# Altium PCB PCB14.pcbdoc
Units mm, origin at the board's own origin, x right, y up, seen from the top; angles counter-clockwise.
Board outline 66.94 x 54.68 mm, 2 copper layers (Top Layer, Bottom Layer); 73 components, 75 nets, 272 pads, 107 vias.
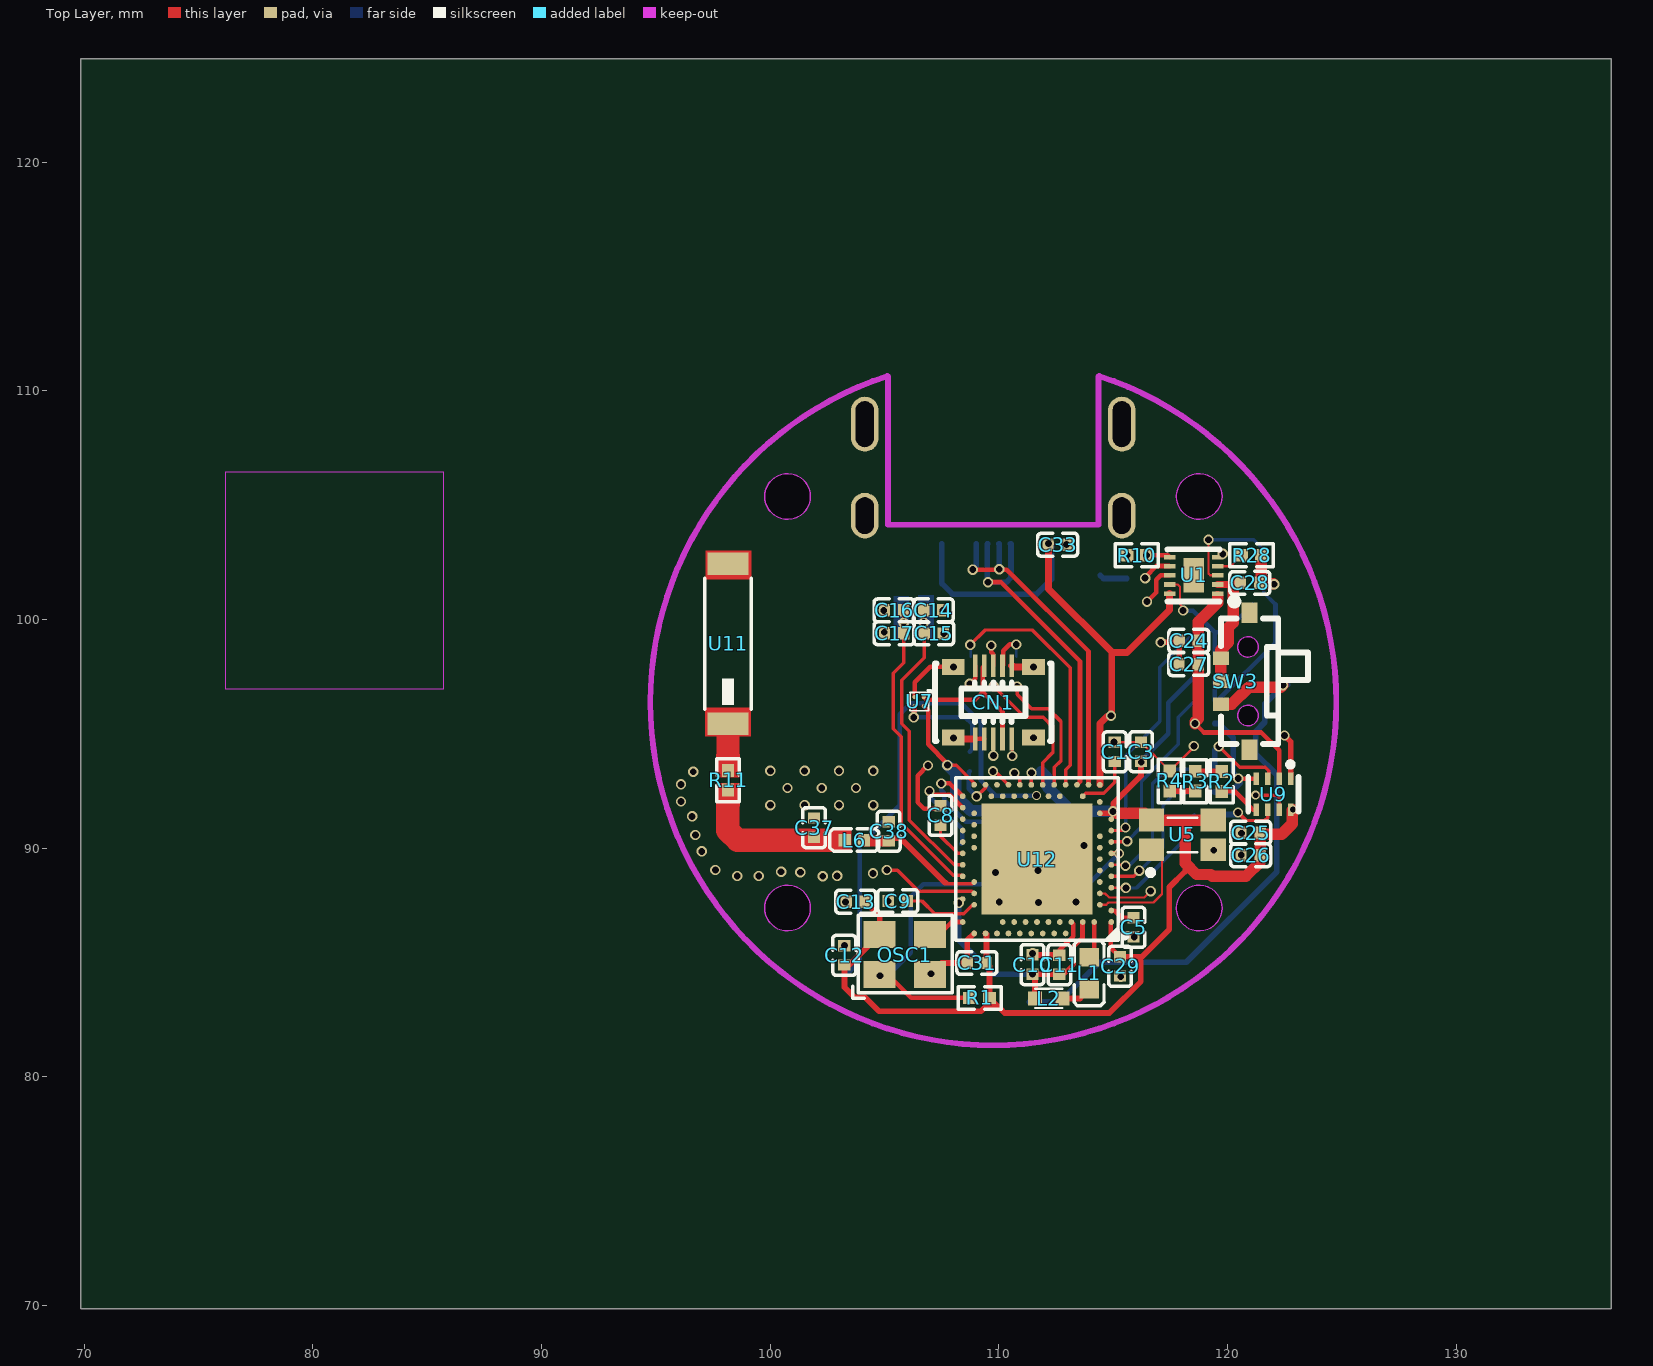
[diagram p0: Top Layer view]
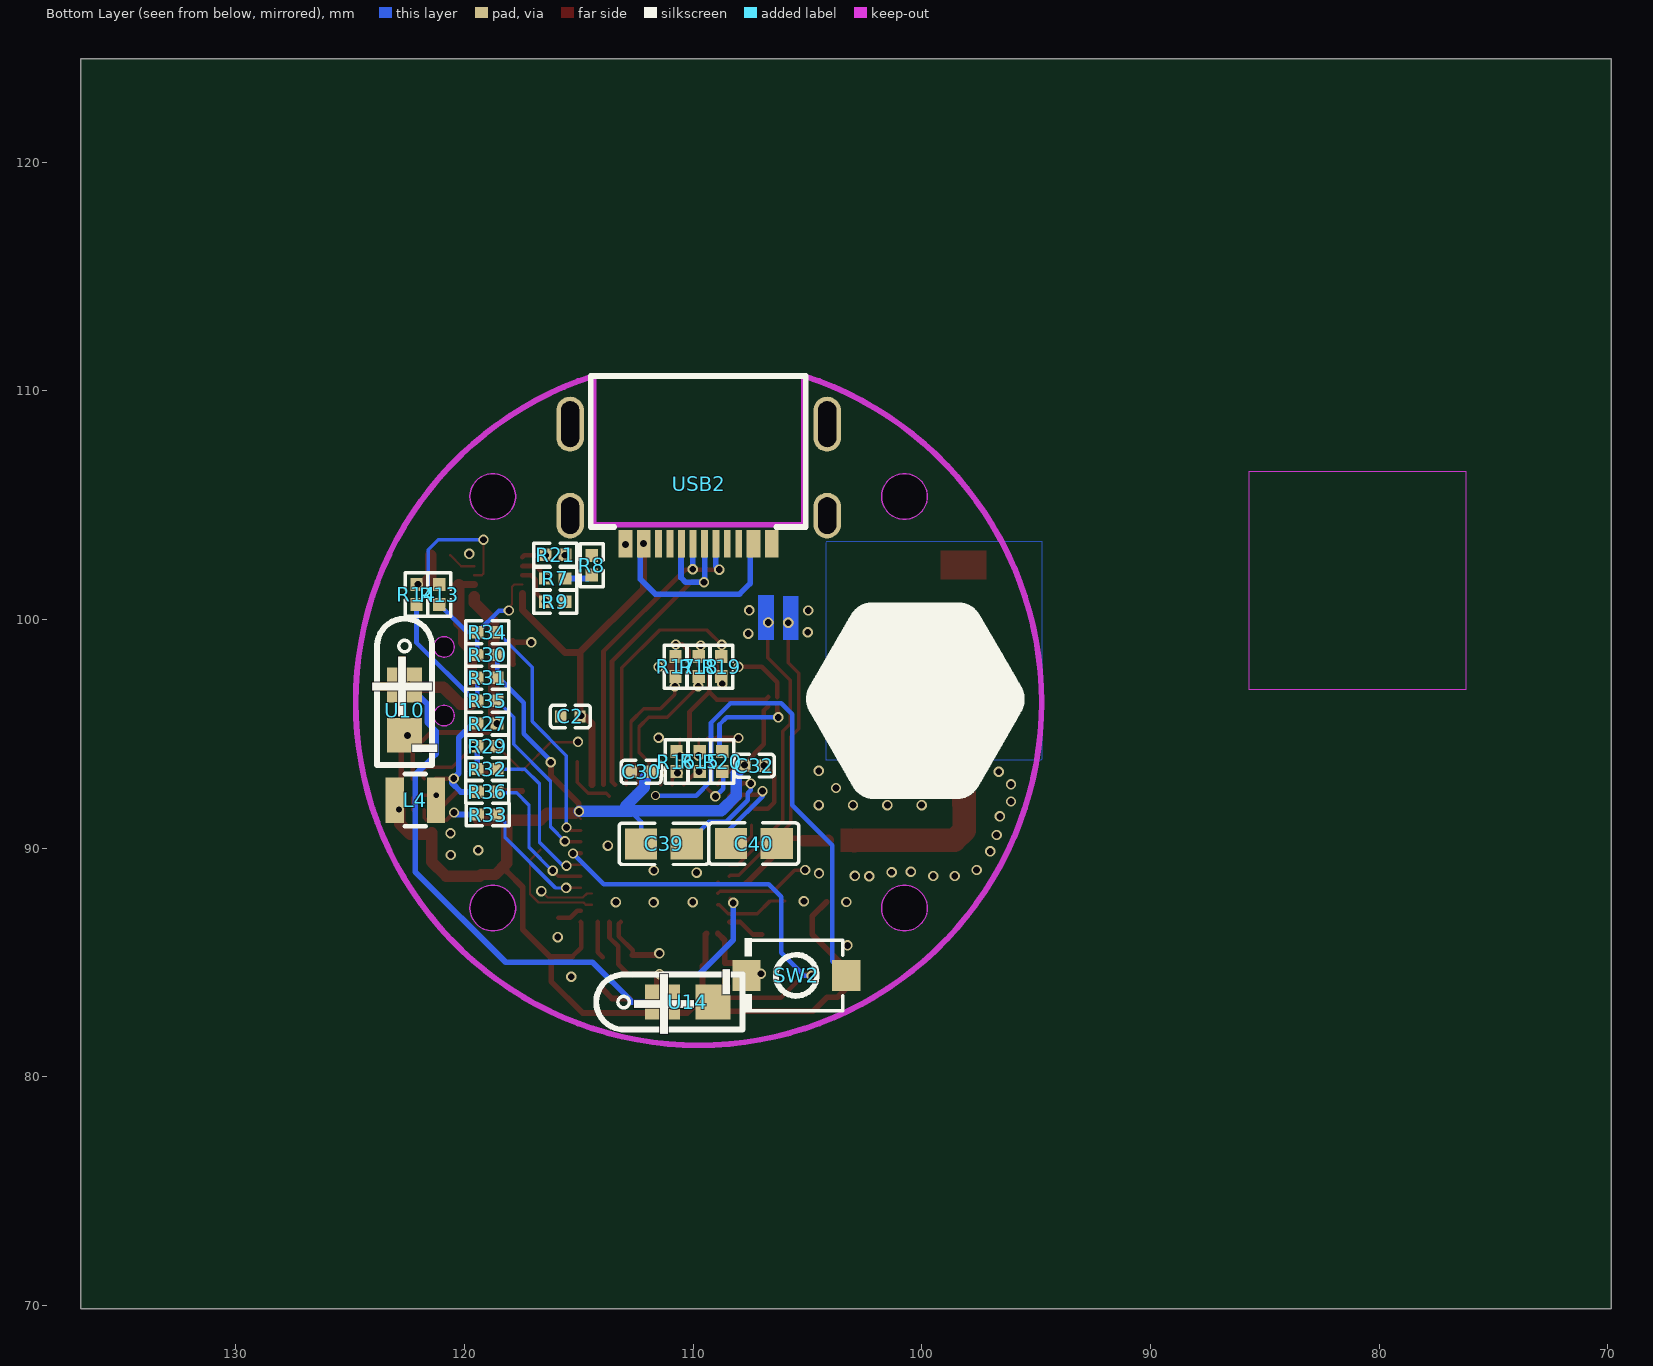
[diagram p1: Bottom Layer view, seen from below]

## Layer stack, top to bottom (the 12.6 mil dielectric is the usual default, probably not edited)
Top Layer: signal copper (thickness not stored)
Dielectric: dielectric 0.32, FR-4, Dk 4.8
Bottom Layer: signal copper (thickness not stored)

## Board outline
136.794,69.85 69.85,69.85 69.85,124.528 136.794,124.528
cut-out: 119.765,105.379 cw(c118.765,105.379) 117.765,105.379 cw(c118.765,105.379)
cut-out: 119.765,87.379 cw(c118.765,87.379) 117.765,87.379 cw(c118.765,87.379)
cut-out: 101.765,87.379 cw(c100.765,87.379) 99.765,87.379 cw(c100.765,87.379)
cut-out: 101.765,105.379 cw(c100.765,105.379) 99.765,105.379 cw(c100.765,105.379)

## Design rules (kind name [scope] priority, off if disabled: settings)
BoardOutlineClearance copperThickness1oz [All] p0: genericclearance=0.254 ignorepadtopadclearanceinfootprint=FALSE except(0: Arc-SplitContinuation Track-SplitContinuation SMDPad-SplitContinuation THPad-SplitContinuation Via-SplitContinuation Fill-SplitContinuation Poly-SplitContinuation Region-SplitContinuation Text-SplitContinuation; 0.152: Track-CutoutEdge SMDPad-CutoutEdge THPad-CutoutEdge Via-CutoutEdge Region-CutoutEdge; 0.3: Track-OutlineEdge SMDPad-OutlineEdge THPad-OutlineEdge Via-OutlineEdge Fill-OutlineEdge Region-OutlineEdge Poly-OutlineEdge Text-OutlineEdge Fill-CutoutEdge)
BoardOutlineClearance copperThickness2oz [All] p0: genericclearance=0.254 ignorepadtopadclearanceinfootprint=FALSE except(0: Arc-SplitContinuation Track-SplitContinuation SMDPad-SplitContinuation THPad-SplitContinuation Via-SplitContinuation Fill-SplitContinuation Poly-SplitContinuation Region-SplitContinuation Text-SplitContinuation; 0.152: Track-CutoutEdge SMDPad-CutoutEdge THPad-CutoutEdge Via-CutoutEdge Region-CutoutEdge; 0.3: Track-OutlineEdge SMDPad-OutlineEdge THPad-OutlineEdge Via-OutlineEdge Fill-OutlineEdge Region-OutlineEdge Poly-OutlineEdge Text-OutlineEdge Fill-CutoutEdge)
Clearance copperThickness1oz [(InNet('GND') OR InNet('DECUSB') OR InNet('VBUS') OR InNet('VDD') OR InNet('DEC1') OR InNet('DEC5') OR InNet('DEC3') OR InNet('DEC4') OR InNet('NFC1') OR InNet('NFC2') OR InNet('ANT') OR InNet('VIN') OR InNet('VBAT') OR InNet('VOUT1') OR InNet('MOSI') OR InNet('CS') OR InNet('MISO') OR InNet('AD_RESET') OR InNet('$1N3350') OR InNet('DCC') OR InNet('$1N6296') OR InNet('CRYST_OE') OR InNet('XC1') OR InNet('$1N6166') OR InNet('$1N6090') OR InNet('$1N6242') OR InNet('$1N7034') OR InNet('$1N6953') OR InNet('$1N7110') OR InNet('$1N7200') OR InNet('STAT2') OR InNet('CE') OR InNet('STAT1') OR InNet('XL1') OR InNet('P0.04') OR InNet('P0.05') OR InNet('SWDCLK') OR InNet('SWDIO') OR InNet('NRESET') OR InNet('D+') OR InNet('D-') OR InNet('OUT_EN') OR InNet('MODE_PWR') OR InNet('EN_PWR') OR InNet('STOP_PWR') OR InNet('$1N13722') OR InNet('DEC2') OR InNet('DCCH') OR InNet('FEED') OR InNet('P0.26') OR InNet('P0.27') OR InNet('P0.06') OR InNet('P0.07') OR InNet('P1.08') OR InNet('P1.09') OR InNet('P1.11') OR InNet('P1.12') OR InNet('P0.14') OR InNet('P0.16') OR InNet('P0.19') OR InNet('P0.21') OR InNet('P0.23') OR InNet('P0.25') OR InNet('P0.13') OR InNet('P0.24') OR InNet('CC1') OR InNet('CC2') OR InNet('SCLK') OR InNet('P0.15') OR InNet('P0.17') OR InNet('P0.20') OR InNet('P0.22') OR InNet('P1.00') OR InNet('VBAT_I') OR InNet('NONE'))] p1: gap=0.178 ignorepadtopadclearanceinfootprint=FALSE except(0.099: Track-Track Track-SMDPad; 0.152: SMDPad-SMDPad Track-THPad SMDPad-THPad THPad-THPad Track-Via SMDPad-Via THPad-Via Via-Via SMDPad-Fill THPad-Fill Via-Fill Fill-Fill Track-Region SMDPad-Region THPad-Region Via-Region Region-Region Track-Poly SMDPad-Poly THPad-Poly Via-Poly Fill-Poly Region-Poly Poly-Poly Track-Text SMDPad-Text THPad-Text Via-Text Fill-Text Region-Text Poly-Text Text-Text; 0.175: SMDPad-Hole THPad-Hole Via-Hole Fill-Hole Region-Hole Poly-Hole Text-Hole Sheet-Hole; 0.201: Track-Hole; 0.3: Track-Fill Fill-Region Track-Sheet SMDPad-Sheet THPad-Sheet Via-Sheet Fill-Sheet Region-Sheet Poly-Sheet Text-Sheet)
Clearance copperThickness2oz [All] p1: gap=0.178 ignorepadtopadclearanceinfootprint=FALSE except(0.152: Track-SMDPad SMDPad-SMDPad Track-THPad SMDPad-THPad THPad-THPad Track-Via SMDPad-Via THPad-Via Via-Via SMDPad-Fill THPad-Fill Via-Fill Fill-Fill Track-Region SMDPad-Region THPad-Region Via-Region Region-Region Track-Poly SMDPad-Poly THPad-Poly Via-Poly Fill-Poly Region-Poly Poly-Poly Track-Text SMDPad-Text THPad-Text Via-Text Fill-Text Region-Text Poly-Text Text-Text; 0.175: Track-Hole SMDPad-Hole THPad-Hole Via-Hole Fill-Hole Region-Hole Poly-Hole Text-Hole Sheet-Hole; 0.203: Track-Track; 0.3: Track-Fill Fill-Region Track-Sheet SMDPad-Sheet THPad-Sheet Via-Sheet Fill-Sheet Region-Sheet Poly-Sheet Text-Sheet)
DiffPairsRouting differentialPair [All] p1: maxuncoupledlength=10 minlimit=6 maxlimit=6 mostfreqgap=6 toplayer_minwidth=5 toplayer_prefwidth=10 toplayer_maxwidth=100 bottomlayer_minwidth=5 bottomlayer_prefwidth=10 bottomlayer_maxwidth=100
PasteMaskExpansion pasteMaskExpansion [All] p1: expansion=0
PlaneConnect innerPlane [All] p1: planeconnectstyle=Relief reliefexpansion=0.508 reliefentries=4 reliefconductorwidth=0.254 reliefairgap=0.254
PolygonConnect copper [All] p1: connectstyle=Direct reliefentries=4 reliefconductorwidth=10 polygonreliefangle="90 Angle" airgapwidth=10
PolygonConnect nocopper [All] p1: connectstyle=No reliefentries=4 reliefconductorwidth=10 polygonreliefangle="90 Angle" airgapwidth=10
PolygonConnect copper_imp [All] p1: connectstyle=Direct reliefentries=4 reliefconductorwidth=10 polygonreliefangle="90 Angle" airgapwidth=10
RoutingVias viaSize [All] p1: viastyle="Through Hole" holewidth=9.8426 minholewidth=3.937 maxholewidth=248.0314 width=15.748 minwidth=7.874 maxwidth=393.7008
SolderMaskExpansion solderMaskExpansion [All] p1: useseparateexpansions=TRUE expansion=2 expansionbottom=2
Width copperThickness1oz [All] p1: maxlimit=100 minlimit=4 preferedwidth=10
Width copperThickness2oz [All] p1: maxlimit=100 minlimit=8 preferedwidth=10

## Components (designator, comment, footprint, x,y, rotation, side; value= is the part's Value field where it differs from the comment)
C1 "CL05A475MP5NRNC" C0402 115.075,94.209 r90 top
C2 "CL05A475MP5NRNC" C0402 115.375,95.759 r0 bottom
C3 "CL05A475MP5NRNC" C0402 116.225,94.219 r90 top
C5 "CL05B104KO5NNNC" C0402 115.895,86.539 r270 top
C8 "0402B102K500NT" C0402 107.455,91.429 r90 top
C9 "0402CG101J500NT" C0402 105.585,87.689 r180 top
C10 "CL05A105KA5NQNC" C0402 111.475,84.909 r270 top
C11 "CL05B104KO5NNNC" C0402 112.655,84.899 r90 top
C12 "CL05B104KO5NNNC" C0402 103.245,85.309 r270 top
C13 "CL05A475MP5NRNC" C0402 103.745,87.659 r0 top
C14 "0402CG101J500NT" C0402 107.134,100.399 r0 top
C15 "0402CG220J500NT" C0402 107.155,99.389 r0 top
C16 "0402CG101J500NT" C0402 105.425,100.399 r180 top
C17 "0402CG220J500NT" C0402 105.425,99.399 r180 top
C24 "CL05A475MP5NRNC" C0402 118.315,99.069 r0 top
C25 "CL05A475MP5NRNC" C0402 121.015,90.679 r0 top
C26 "CL05A475MP5NRNC" C0402 121.015,89.689 r0 top
C27 "CL05A105KA5NQNC" C0402 118.305,98.049 r180 top
C28 "CL05A105KA5NQNC" C0402 120.985,101.599 r0 top
C29 "CL05A105KA5NQNC" C0402 115.305,84.829 r270 top
C30 "CL05B104KO5NNNC" C0402 112.285,93.339 r0 bottom
C31 "CL05B104KO5NNNC" C0402 109.045,84.979 r180 top
C32 "CL05B104KO5NNNC" C0402 107.335,93.609 r180 bottom
C33 "CL05A105KA5NQNC" C0402 112.575,103.269 r0 top
C37 "RF15N0R5A500CT" C0402 101.925,90.899 r90 top
C38 "RF15N0R8B500CT_C396870" C0402 105.185,90.739 r270 top
C39 "CL21A106KAYNNNE_C15850" C0805 111.285,90.189 r180 bottom
C40 "CL21A106KAYNNNE_C15850" C0805 107.355,90.199 r0 bottom
CN1 "513389873" CONN-SMD_513389873 109.765,96.379 r0 top
L1 "LQM18DN100M70L" L0603 113.955,84.529 r90 top
L2 "AISC-0402-15NJ-T" IND-SMD_L1.2-W0.6 112.185,83.429 r0 top
L4 "WIP201610P-2R2ML" IND-SMD_L2.0-W1.6_MHCHL201610A-1R0M-Q8A 122.155,92.099 r0 bottom
L6 "VHF100505HQ4N7ST" L0402 103.685,90.349 r180 top
OSC1 "OT2EL89CJI-111YLC-32M" OSC-SMD_4P-L3.2-W2.5-BL 105.895,85.349 r0 top
R1 "0402WGF2003TCE" R0402 109.165,83.449 r180 top
R2 "0402WGF2003TCE" R0402 119.755,92.919 r90 top
R3 "0402WGF3302TCE" R0402 118.595,92.929 r270 top
R4 "0402WGF3302TCE" R0402 117.482,92.938 r90 top
R7 "0402WGF5102TCE" R0402 116.037,101.791 r180 bottom
R8 "0402WGF5101TCE" R0402 114.435,102.369 r90 bottom
R9 "0402WGF5100TCE" R0402 116.035,100.779 r180 bottom
R10 "0402WGF1002TCE" R0402 116.037,102.807 r180 top
R11 "CRCW04020000Z0EDHP" R0402 98.164,92.97 r90 top
R13 "CRCW04020000Z0EDHP" R0402 121.105,101.089 r270 bottom
R14 "CRCW04020000Z0EDHP" R0402 122.105,101.089 r270 bottom
R15 "CRCW04020000Z0EDHP" R0402 109.725,93.789 r90 bottom
R16 "CRCW04020000Z0EDHP" R0402 110.735,93.789 r90 bottom
R17 "CRCW04020000Z0EDHP" R0402 110.775,97.939 r90 bottom
R18 "CRCW04020000Z0EDHP" R0402 109.765,97.939 r90 bottom
R19 "CRCW04020000Z0EDHP" R0402 108.775,97.939 r270 bottom
R20 "CRCW04020000Z0EDHP" R0402 108.735,93.789 r90 bottom
R21 "0402WGF1002TCE" R0402 116.042,102.829 r180 bottom
R27 "0402WGF2003TCE" R0402 119.015,95.449 r0 bottom
R28 "0402WGF2003TCE" R0402 121.055,102.809 r0 top
R29 "0402WGF2003TCE" R0402 119.015,94.449 r180 bottom
R30 "0402WGF2003TCE" R0402 119.015,98.449 r0 bottom
R31 "0402WGF2003TCE" R0402 119.015,97.449 r0 bottom
R32 "CRCW04020000Z0EDHP" R0402 119.015,93.459 r0 bottom
R33 "CRCW04020000Z0EDHP" R0402 118.995,91.469 r0 bottom
R34 "CRCW04020000Z0EDHP" R0402 119.015,99.439 r0 bottom
R35 "CRCW04020000Z0EDHP" R0402 119.015,96.449 r0 bottom
R36 "CRCW04020000Z0EDHP" R0402 119.005,92.459 r0 bottom
SW2 "TS-1088-AR02016" SW-SMD_L3.9-W3.0-P4.45 105.495,84.439 r0 bottom
SW3 "MK-11C04-G013" SW-SMD_MK-11C04-G013 120.345,97.299 r90 top
U1 "BQ25185DLHR" WSON-10_L2.2-W2.0-P0.40-BL-EP_TI_DLH0010A 118.525,101.929 r90 top
U5 "OV-7604-C7-32.768kHz-20PPM-TA-QC" OSC-SMD_4P-L3.2-W1.5-BL 118.035,90.579 r0 top
U7 "TPS22916BYFPR" DSBGA-4_L0.8-W0.8-R2-C2-P0.40-BL 106.525,96.409 r180 top
U9 "TPS62840DLCR" VSON-8_L2.0-W1.5-P0.50-BL 122.015,92.359 r180 top
U10 "CSSMR950SH_CONN" CSSMR950SH_CONN 122.625,93.839 r180 bottom
U11 "2450AT43A100E" ANT-SMD_L7.0-W2.0-R 98.164,98.939 r270 top
U12 "NRF52840-QIAA-R7" AQFN-73_L7.0-W7.0-P0.50-BL-EP4.8 111.675,89.521 r90 top
U14 "CSSMR950SH_CONN" CSSMR950SH_CONN 108.045,83.269 r90 bottom
USB2 "TYPE-C-31-M-13" USB-C-SMD_TYPE-C-31-M-13 109.765,105.929 r0 bottom

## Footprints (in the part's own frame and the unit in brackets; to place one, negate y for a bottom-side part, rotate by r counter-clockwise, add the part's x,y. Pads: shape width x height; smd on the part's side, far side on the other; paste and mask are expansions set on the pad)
ANT-SMD_L7.0-W2.0-R [mm]
  rect 1x1.8 smd: 1(3.5,0) 2(-3.5,0)
  silkscreen extent -2.86,-1.02 2.86,1.02
AQFN-73_L7.0-W7.0-P0.50-BL-EP4.8 [mm]
  rect 4.85x4.85 smd: 0(0,0)
  round 0.25 smd: A8(-3.25,-1.25) A10(-3.25,-0.75) A12(-3.25,-0.25) A14(-3.25,0.25) A16(-3.25,0.75) A18(-3.25,1.25) A20(-3.25,1.75) A22(-3.25,2.25) A23(-3.25,2.75) AA24(2.25,3.25) AB2(2.5,-2.75) AC5(2.75,-2) AC9(2.75,-1) AC11(2.75,-0.5) AC13(2.75,0) AC15(2.75,0.5) AC17(2.75,1) AC19(2.75,1.5) AC21(2.75,2) AC24(2.75,3.25) AD2(3.25,-2.75) AD4(3.25,-2.25) AD6(3.25,-1.75) AD8(3.25,-1.25) AD10(3.25,-0.75) AD12(3.25,-0.25) AD14(3.25,0.25) AD16(3.25,0.75) AD18(3.25,1.25) AD20(3.25,1.75) AD22(3.25,2.25) AD23(3.25,2.75) B1(-2.75,-3.25) B3(-2.75,-2.5) B5(-2.75,-2) B7(-2.75,-1.5) B9(-2.75,-1) B11(-2.75,-0.5) B13(-2.75,0) B15(-2.75,0.5) B17(-2.75,1) B19(-2.75,1.5) B24(-2.75,3.25) C1(-2.25,-3.25) D2(-2,-2.75) D23(-2,2.75) E24(-1.75,3.25) F2(-1.5,-2.75) F23(-1.5,2.75) G1(-1.25,-3.25) H2(-1,-2.75) H23(-1,2.75) J1(-0.75,-3.25) J24(-0.75,3.25) K2(-0.5,-2.75) L1(-0.25,-3.25) L24(-0.25,3.25) M2(0,-2.75) N1(0.25,-3.25) N24(0.25,3.25) P2(0.5,-2.75) P23(0.5,2.75) R1(0.75,-3.25) R24(0.75,3.25) T2(1,-2.75) T23(1,2.75) U1(1.25,-3.25) U24(1.25,3.25) V23(1.5,2.75) W1(1.75,-3.25) W24(1.75,3.25) Y2(2,-2.75) Y23(2,2.75)
  silkscreen extent -3.55,-3.95 3.55,3.55
C0402 [mm]
  rect 0.5x0.54 smd: 1(-0.42,0) 2(0.42,0)
  silkscreen extent -0.87,-0.5 0.87,0.5
C0805 [mm]
  rect 1.41x1.35 smd: 1(-1,0) 2(1,0)
  silkscreen extent -1.96,-0.9 1.96,0.9
CONN-SMD_513389873 [mm]
  rect 0.2x1 smd: 1(-0.8,-1.6) 2(-0.8,1.6) 3(-0.4,-1.6) 4(-0.4,1.6) 5(0,-1.6) 6(0,1.6) 7(0.4,-1.6) 8(0.4,1.6) 9(0.8,-1.6) 10(0.8,1.6)
  rect 1x0.7 smd: 11(1.75,1.55) 12(1.75,-1.55) 13(-1.75,-1.55) 14(-1.75,1.55)
  silkscreen extent -2.55,-1.7 2.55,1.7
CSSMR950SH_CONN [mil]
  rect 60x60 smd: 1(0,130) 2(0,43.31)
  silkscreen extent -47,-8 47,244
DSBGA-4_L0.8-W0.8-R2-C2-P0.40-BL [mm]
  round 0.18 smd: A1(-0.2,-0.2) A2(-0.2,0.2) B1(0.2,-0.2) B2(0.2,0.2)
  silkscreen extent -0.51,-0.51 0.4,0.4
IND-SMD_L1.2-W0.6 [mm]
  rect 0.6x0.6 smd: 1(-0.6,0) 2(0.6,0)
  silkscreen extent -0.6,-0.42 0.6,0.42
IND-SMD_L2.0-W1.6_MHCHL201610A-1R0M-Q8A [mm]
  rect 0.8x2 smd: 1(-0.9,0) 2(0.9,0)
  silkscreen extent -0.46,-1.14 0.46,1.14
L0402 [mm]
  rect 0.54x0.54 smd: 1(-0.42,0) 2(0.42,0)
  silkscreen extent -1.07,-0.51 1.07,0.49
L0603 [mm]
  rect 0.8x0.864 smd: 1(-0.7,0) 2(0.7,0)
  silkscreen extent -1.42,-0.65 1.42,0.65
OSC-SMD_4P-L3.2-W1.5-BL [mm]
  rect 1.1x1 smd: 1(-1.35,-0.65) 2(1.35,-0.65) 3(1.35,0.65) 4(-1.35,0.65)
  silkscreen extent -1.52,-1.77 0.65,0.75
OSC-SMD_4P-L3.2-W2.5-BL [mm]
  rect 1.4x1.2 smd: 1(-1.1,-0.875) 2(1.1,-0.875) 3(1.1,0.875) 4(-1.1,0.875)
  silkscreen extent -2.29,-1.9 2.07,1.72
R0402 [mm]
  rect 0.566x0.54 smd: 1(-0.433,0) 2(0.433,0)
  silkscreen extent -0.94,-0.5 0.94,0.5
SW-SMD_L3.9-W3.0-P4.45 [mm]
  rect 1.23x1.36 smd: 1(-2.185,0) 2(2.185,0)
  silkscreen extent -2.03,-1.62 2.25,1.62
SW-SMD_MK-11C04-G013 [mm]
  rect 0.6x0.7 smd: 1(-1,0.63) 2(1,0.63) C(0,0.63)
  rect 0.9x0.7 smd: 4(3,-0.63) 5(-3,-0.63)
  Board Outline Layer circle w0.005: c-1.5,-0.555 r0.45
  Board Outline Layer circle w0.005: c1.5,-0.555 r0.45
  Board Outline Layer region: -1.5,-1.005 -1.695,-0.961 -1.852,-0.836 -1.939,-0.655 -1.939,-0.455 -1.852,-0.274 -1.695,-0.15 -1.5,-0.105 -1.5,-0.105 -1.305,-0.15 -1.148,-0.274 -1.061,-0.455 -1.061,-0.655 -1.148,-0.836 -1.305,-0.961 -1.5,-1.005
  Board Outline Layer region: 1.5,-1.005 1.305,-0.961 1.148,-0.836 1.061,-0.655 1.061,-0.455 1.148,-0.274 1.305,-0.15 1.5,-0.105 1.5,-0.105 1.695,-0.15 1.852,-0.274 1.939,-0.455 1.939,-0.655 1.852,-0.836 1.695,-0.961 1.5,-1.005
  Multi-Layer board cut-out: -1.5,-1.005 -1.695,-0.961 -1.852,-0.836 -1.939,-0.655 -1.939,-0.455 -1.852,-0.274 -1.695,-0.15 -1.5,-0.105 -1.5,-0.105 -1.305,-0.15 -1.148,-0.274 -1.061,-0.455 -1.061,-0.655 -1.148,-0.836 -1.305,-0.961 -1.5,-1.005
  Multi-Layer board cut-out: 1.5,-1.005 1.305,-0.961 1.148,-0.836 1.061,-0.655 1.061,-0.455 1.148,-0.274 1.305,-0.15 1.5,-0.105 1.5,-0.105 1.695,-0.15 1.852,-0.274 1.939,-0.455 1.939,-0.655 1.852,-0.836 1.695,-0.961 1.5,-1.005
  silkscreen extent -2.75,-3.18 2.75,0.62
USB-C-SMD_TYPE-C-31-M-13 [mm]
  oval 1.2x2.4 hole 0.8 slot 2 at 90 deg: 0(-5.62,-2.612) 0(5.62,-2.612)
  oval 1.2x2 hole 0.8 slot 1.6 at 90 deg: 0(-5.62,1.388) 0(5.62,1.388)
  rect 0.3x1.2 smd: A1(-3.35,2.612) A4(-2.55,2.612) A5(-1.25,2.612) A6(-0.25,2.612) A7(0.25,2.612) A8(1.25,2.612) A9(2.55,2.612) A12(3.35,2.612) B1(3.05,2.612) B4(2.25,2.612) B5(1.75,2.612) B6(0.75,2.612) B7(-0.75,2.612) B8(-1.75,2.612) B9(-2.25,2.612) B12(-3.05,2.612)
  Board Outline Layer lines w0.254: -4.6,1.789 4.6,1.789 ; -4.6,1.789 -4.6,-4.7 -4.6,1.789 ; -4.6,1.789 4.6,1.789 ; 4.6,1.789 4.6,-4.7 4.6,1.789
  silkscreen extent -4.68,-4.71 4.72,1.89
VSON-8_L2.0-W1.5-P0.50-BL [mm]
  rect 0.25x0.55 smd: 1(-0.75,-0.675) 2(-0.25,-0.675) 3(0.25,-0.675) 4(0.75,-0.675) 5(0.75,0.675) 6(0.25,0.675) 7(-0.25,0.675) 8(-0.75,0.675)
  silkscreen extent -1.1,-1.4 1.1,0.75
WSON-10_L2.2-W2.0-P0.40-BL-EP_TI_DLH0010A [mm]
  rect 0.2x0.5 smd: 1(-0.8,-1.05) 2(-0.4,-1.05) 3(0,-1.05) 4(0.4,-1.05) 5(0.8,-1.05) 6(0.8,1.05) 7(0.4,1.05) 8(0,1.05) 9(-0.4,1.05) 10(-0.8,1.05)
  rect 1.5x0.9 smd: 11(0,0)
  silkscreen extent -1.45,-2.08 1.14,1.14

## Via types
v1: diameter 0.45, hole 0.3, Top Layer to Bottom Layer, 104 vias
v2: diameter 0.4, hole 0.25, Top Layer to Bottom Layer, 2 vias
v3: diameter 0.4, hole 0.3, Top Layer to Bottom Layer, 1 vias

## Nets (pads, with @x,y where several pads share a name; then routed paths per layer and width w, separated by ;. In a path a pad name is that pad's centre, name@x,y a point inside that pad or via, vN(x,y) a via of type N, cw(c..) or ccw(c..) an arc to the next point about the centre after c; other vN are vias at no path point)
$1N3350: L1.1 L2.2 | length 1.3
  Top Layer w0.25: L2.2 113.554,83.429 L1.1
$1N6090: R2.1 U9.5 | length 1.8
  Top Layer w0.2: R2.1 120.317,92.486 121.12,91.684 U9.5
$1N6166: R2.2 R3.1 | length 1.2
  Top Layer w0.254: R3.1 118.605,93.352 R2.2
$1N6242: R3.2 R4.1 | length 1.1
  Top Layer w0.254: R4.1 117.49,92.496 R3.2
$1N6296: L4.1 U9.7 | length 1.6
  Top Layer w0.15: v2(121.235,92.319) 122.155,92.319 122.265,92.209 U9.7
$1N6953: R7.1 U1.7 | length 1.3
  Top Layer w0.2: v1(116.405,101.809) 116.405,101.849 116.895,102.339 117.465,102.339 U1.7
$1N7034: R7.2 R8.1 | length 1.2
  Bottom Layer w0.25: R8.1 114.58,101.791 R7.2
$1N7110: R9.1 U1.8 | length 1.8
  Top Layer w0.2: v1(116.485,100.779) 116.885,101.179 116.885,101.729 117.085,101.929 U1.8
$1N7200: R10.1 R21.1 U1.6 | length 1
  Top Layer w0.2: R10.1 117.397,102.807 U1.6
  other v1: 116.465,102.809
$1N13722: R11.2 U11.1 | length 1.7
  Top Layer w1.018: 98.164,93.732 U11.1
AD_RESET: CN1.9 R16.2 | length 0.8
  Top Layer w0.1: CN1.9 110.595,94.749 v1(110.595,94.029)
ANT: C38.2 L6.1 U12.H23 | length 5.6
  Top Layer w0.15: 107.685,88.449 108.853,88.449 U12.H23
  Top Layer w0.255: C38.2@105.285,90.319 105.4,90.434 105.71,90.434 107.655,88.489 107.685,88.489
  Top Layer w0.5: L6.1 104.135,90.319 C38.2
CC1: USB2.A5
CC2: USB2.B5
CE: R28.1 U1.4 | length 1.2
  Top Layer w0.1: U1.4 120.142,102.329 R28.1
CRYST_OE: OSC1.1 R1.2 U12.N1 | length 18.7
  Top Layer w0.2: OSC1.1 105.147,84.474 106.172,83.449 R1.2 ; U12.N1 v1@115.194,89.771
  Bottom Layer w0.2: v1(104.815,84.419) 105.155,84.419 106.155,85.419 106.155,87.869 106.705,88.419 113.915,88.419 v1(115.265,89.769)
CS: CN1.6 R18.2 | length 0.9
  Top Layer w0.2: v1(109.675,98.859) 109.675,98.576 109.764,98.487 CN1.6
D+: U12.AD6 USB2.A6 USB2.B6 | length 15.2
  Top Layer w0.2: v1@109.545,101.639 110.095,101.639 113.555,98.179 113.555,92.9 U12.AD6
  Bottom Layer w0.25: USB2.A6 109.495,103.297 109.495,101.669 v1(109.535,101.629) 110.335,101.629 110.535,101.829 110.535,103.297 USB2.B6
D-: U12.AD4 USB2.A7 USB2.B7 | length 14.7
  Top Layer w0.2: v1(108.865,102.179) 110.355,102.179 113.925,98.609 U12.AD4
  Bottom Layer w0.25: v1(108.865,102.179) 109.015,102.329 USB2.B7 ; USB2.A7 110.025,103.307 v1(110.025,102.199)
DCC: L1.2 U12.B3 | length 1.6
  Top Layer w0.2: L1.2 114.175,85.449 U12.B3
DCCH: U12.AB2
DEC1: C5.1 U12.C1 | length 1.1
  Top Layer w0.2: U12.C1 115.066,87.271 115.378,86.959 C5.1
DEC2: U12.A18
DEC3: C9.1 U12.D23 | length 3.3
  Top Layer w0.15: C9.1 106.645,87.689 107.195,87.139 108.476,87.139 108.858,87.521 U12.D23
DEC4: C10.2 C11.1 L2.1 U12.B5 U12.E24 | length 10.8
  Top Layer w0.1: v1(111.475,84.489) C10.2@111.585,84.379
  Top Layer w0.15: v1(108.255,87.609) 108.387,87.741 U12.E24@108.387,87.809
  Top Layer w0.2: C11.1 112.844,84.479 113.285,84.919 113.285,85.709 113.665,86.089 113.665,86.76 U12.B5
  Top Layer w0.25: v1(111.475,84.489) 112.645,84.489 C11.1 ; L2.1 C10.2@111.585,84.379
  Bottom Layer w0.25: v1(108.255,87.609) 108.255,85.989 109.755,84.489 v1(111.475,84.489)
DEC5: C8.1 U12.N24 | length 1.8
  Top Layer w0.15: C8.1 107.455,90.519 108.203,89.771 U12.N24
DECUSB: C1.1 U12.AC5 | length 2.6
  Top Layer w0.15: U12.AC5 113.803,92.399 114.584,92.399 115.075,92.889 C1.1
EN_PWR: R27.2 R36.2 U9.4 | length 5.4
  Top Layer w0.1: v1(120.478,93.049) v1@120.493,93.034
  Top Layer w0.2: v1@120.493,93.034 U9.4
  Bottom Layer w0.25: R36.2 120.165,92.459 120.565,92.859 120.565,93.099 120.515,93.049 v1(120.478,93.049) 120.255,93.272 120.255,94.829 119.635,95.449 R27.2
FEED: C37.1 L6.2 R11.1 | length 6.4
  Top Layer w1.018: 98.157,92.213 98.157,90.773 98.581,90.349 102.945,90.349 102.965,90.329
GND: C1.2 C2.2 C3.2 C5.2 C8.2 C9.2 C10.1 C11.2 C12.1 C13.1 C14.2 C15.2 C16.2 C17.2 C24.1 C25.1 C26.1 C27.2 C28.2 C29.2 C30.2 C31.2 C32.2 C33.2 C37.2 C38.1 C40.1 CN1.1 CN1.3 CN1.10 CN1.11 CN1.12 CN1.13 CN1.14 OSC1.2 R4.2 R8.2 R9.2 R10.2 R13.1 R14.1 R21.2 R28.2 R29.2 SW2.2 U1.5 U5.2 U7.B1 U9.1 U10.2 U12.0 U12.A23 U12.B7 U12.F2 U12.F23 U14.2 USB2.A1 USB2.A12 USB2.B1 USB2.B12 | length 30.9
  Top Layer w0.1: U12.F2 114.653,88.021 114.835,87.838 116.364,87.838 v1(116.645,88.119) ; C1.2 116.215,94.629 C3.2 117.482,93.382 R4.2 118.535,94.424 v1(118.535,94.469) ; R10.2@115.599,102.802 R10.2 ; C24.1@117.824,98.999 C24.1
  Top Layer w0.15: v1(105.109,89.041) 105.573,89.041 106.491,88.123 108.823,88.123 U12.F23
  Top Layer w0.2: U7.B1 106.325,97.249 107.005,97.929 v1(108.025,97.929) ; v1(106.905,93.619) 106.455,93.169 106.455,91.999 106.735,91.719 107.324,91.719 C8.2 ; CN1.1 CN1.3 ; C11.2 112.655,85.539 113.255,86.139 113.255,86.691 U12.B7
  Top Layer w0.25: v1(107.035,84.509) 107.505,84.979 C31.2 108.624,85.97 U12.A23 ; C10.1 112.645,85.329 C11.2 ; v1(117.085,98.999) C24.1@117.824,98.999 ; C27.2 117.894,98.059 C24.1 ; v1(122.495,94.929) 122.765,94.659 U9.1
  Top Layer w0.3: v1(108.025,94.819) 108.065,94.779 CN1.1 ; CN1.10 110.605,97.979 110.655,97.929 v1(111.515,97.929)
  Top Layer w0.5: C28.2 121.487,101.682 C28.2@121.487,101.846 ; R28.2 C28.2@121.487,101.846 ; v1@122.015,101.559 121.775,101.559 C28.2@121.487,101.846
  other v1: 115.335,84.379 111.485,85.399 103.255,85.749 115.925,86.109 110.025,87.639 111.735,87.629 113.385,87.639 103.305,87.649 105.165,87.679 98.565,88.779 99.505,88.779 102.305,88.769 102.935,88.789 104.505,88.899 109.855,88.929 101.325,88.949 100.485,88.969 111.725,89.019 97.609,89.041 120.605,89.699 97.015,89.859 119.405,89.909 113.735,90.109 96.735,90.579 120.615,90.649 96.595,91.389 100.013,91.882 101.513,91.882 103.013,91.882 104.513,91.882 96.109,92.041 100.763,92.632 102.263,92.632 103.763,92.632 96.109,92.791 96.645,93.339 100.013,93.382 101.513,93.382 103.013,93.382 104.513,93.382 115.045,94.649 111.515,94.829 107.595,99.379 104.995,99.439 104.975,100.389 107.555,100.399 122.045,101.539 115.605,102.809 119.795,102.869 112.965,103.279
MISO: CN1.8 R17.2 | length 1.9
  Top Layer w0.2: CN1.8 110.195,98.009 110.195,98.629 110.475,98.909 v1(110.765,98.909)
  Bottom Layer w0.1: v1(110.765,98.909) 110.765,98.382 R17.2
MODE_PWR: R29.1 R32.2 U9.3 | length 4.1
  Top Layer w0.15: v1(119.625,94.449) 120.545,93.529 121.652,93.529 121.805,93.376 121.805,93.074 U9.3
  Bottom Layer w0.25: R32.2 119.447,94.282 119.615,94.449 v1(119.625,94.449)
MOSI: CN1.5 R15.2 | length 0.7
  Top Layer w0.1: v1(109.764,94.046) CN1.5
NFC1: C14.1 C15.1 U12.L24 | length 12.9
  Top Layer w0.1: C14.1 106.734,100.379 C15.1
  Top Layer w0.15: C15.1 106.734,98.319 105.765,97.349 105.765,95.449 106.095,95.119 106.095,91.229 108.053,89.271 U12.L24
  other v1: 106.725,99.869
NFC2: C16.1 C17.1 U12.J24 | length 13.3
  Top Layer w0.1: C17.1 v1(105.845,99.859) C16.1
  Top Layer w0.15: C17.1 105.845,98.109 105.385,97.649 105.385,95.229 105.735,94.879 105.735,91.089 108.005,88.819 108.377,88.819 U12.J24
NONE: 
NRESET: SW2.1 U12.AC13 | length 21.7
  Bottom Layer w0.2: SW2.1 103.925,85.054 103.925,90.119 105.675,91.869 105.675,95.849 106.155,96.329 ; 106.145,96.329 106.155,96.329 ; v3(111.652,92.297) 109.877,92.297 109.225,92.949 109.225,95.479 108.375,96.329 106.155,96.329
OUT_EN: R20.2 U7.B2 | length 4.4
  Top Layer w0.2: v1(106.285,95.719) 106.285,95.949 106.325,95.989 U7.B2
  Bottom Layer w0.2: v1(106.285,95.719) 108.545,95.719 108.855,95.409 108.855,94.342 R20.2
P0.04: R36.1 U12.J1 | length 6.3
  Top Layer w0.15: U12.J1 115.897,88.771 v1(116.143,89.017)
  Bottom Layer w0.15: v1(116.143,89.017) 116.162,89.017 117.185,90.039 117.185,91.879 117.725,92.419 118.532,92.419 R36.1
P0.05: U12.K2
P0.06: R32.1 U12.L1 | length 6.9
  Top Layer w0.1: U12.L1 115.503,89.271 v1(115.542,89.232)
  Bottom Layer w0.15: v1(115.542,89.232) 115.697,89.232 116.725,90.259 116.725,92.819 117.365,93.459 R32.1
P0.07: U12.M2
P0.13: R19.1 U12.AD8 | length 11
  Top Layer w0.15: v1(108.755,98.889) 108.765,98.889 109.415,99.539 111.475,99.539 113.125,97.889 113.125,93.629 112.925,93.429 U12.AD8
  Bottom Layer w0.1: v1(108.755,98.889) 108.775,98.869 R19.1
P0.14: U12.AC9
P0.15: R17.1 U12.AD10 | length 5.7
  Top Layer w0.15: v1(110.805,97.069) 110.805,96.719 111.435,96.089 112.175,96.089 112.725,95.539 112.725,93.829 112.426,93.531 U12.AD10
P0.16: U12.AC11
P0.17: R18.1 U12.AD12 | length 6
  Top Layer w0.15: v1(109.785,97.079) 111.145,95.719 111.955,95.719 112.375,95.299 112.375,94.189 111.925,93.739 U12.AD12
P0.19: U12.AC15
P0.20: R16.1 U12.AD16 | length 0.6
  Top Layer w0.15: v1(110.683,93.287) 110.925,93.046 U12.AD16
P0.21: U12.AC17
P0.22: R15.1 U12.AD18 | length 0.9
  Top Layer w0.15: v1(109.755,93.359) 109.837,93.359 U12.AD18
P0.23: U12.AC19
P0.24: U12.AD20
P0.25: U12.AC21
P0.26: R33.1 U12.G1 | length 5.4
  Top Layer w0.1: U12.G1 115.553,88.271 v1(115.558,88.265)
  Bottom Layer w0.15: v1(115.558,88.265) 115.565,88.259 116.025,88.259 118.235,90.469 118.235,91.142 R33.1
P0.27: U12.H2
P1.00: R20.1 U12.AD22 | length 1.9
  Top Layer w0.15: v1(109.036,92.265) 109.425,92.654 U12.AD22
  Bottom Layer w0.2: R20.1 108.695,93.316 108.695,92.606 v1(109.036,92.265)
P1.08: U12.P2
P1.09: R35.1 U12.R1 | length 8.1
  Top Layer w0.15: U12.R1 115.585,90.271 v1(115.615,90.3)
  Bottom Layer w0.15: v1(115.615,90.3) 116.245,90.93 116.245,92.929 117.855,94.539 117.855,95.722 R35.1
P1.11: U12.T2
P1.12: R34.1 U12.U1 | length 10.5
  Top Layer w0.1: v1@115.415,90.771 v1(115.547,90.902)
  Top Layer w0.15: U12.U1 v1@115.415,90.771
  Bottom Layer w0.15: v1(115.547,90.902) 115.547,94.041 117.045,95.539 117.045,97.902 R34.1
SCLK: CN1.2 R19.2 | length 0.9
  Top Layer w0.2: v1(108.735,97.189) 108.965,97.419 CN1.2
STAT1: R13.2 R30.2 R34.2 U1.9 | length 6.5
  Top Layer w0.1: U1.9 117.824,101.529 117.925,101.429 117.925,100.671 118.065,100.531 v1(118.065,100.389)
  Bottom Layer w0.2: v1(118.065,100.389) 118.497,100.389 R34.2 ; R30.2 R34.2 ; R13.2 119.887,99.439 R34.2
STAT2: R14.2 R31.2 R35.2 U1.3 | length 13.5
  Top Layer w0.1: v1(119.175,103.489) 119.175,102.009 119.255,101.929 U1.3
  Bottom Layer w0.15: v1(119.175,103.489) 121.145,103.489 121.585,103.049 121.585,101.176 R14.2
  Bottom Layer w0.2: R31.2 R35.2 119.565,96.449 122.105,98.989 R14.2
STOP_PWR: R33.2 U9.6 | length 2.9
  Top Layer w0.15: v1(120.465,91.559) 120.815,91.209 121.645,91.209 121.765,91.329 U9.6
  Bottom Layer w0.25: R33.2 120.375,91.469 v1(120.465,91.559)
SWDCLK: C40.2 U12.AA24 | length 4.7
  Top Layer w0.2: v1(106.97,92.492) 107.133,92.329 107.867,92.329 U12.AA24
  Bottom Layer w0.2: v1(106.97,92.492) 106.97,92.263 108.415,90.819 108.415,90.259 C40.2
SWDIO: C39.2 U12.AC24 | length 5.4
  Top Layer w0.2: v1(107.485,92.829) 107.867,92.829 U12.AC24
  Bottom Layer w0.2: v1(107.485,92.829) 107.485,92.534 107.625,92.394 107.625,92.096 108.561,91.159 109.315,91.159 C39.2
VBAT: C28.1 SW3.2 SW3.C U1.2 | length 5.5
  Top Layer w0.1: 120.248,101.529 120.495,101.529 C28.1
  Top Layer w0.3: U1.2 120.248,101.529
  Top Layer w0.5: SW3.C SW3.2 119.715,98.659 120.048,98.992 120.048,99.652 120.248,99.852 120.248,101.529
VBAT_I: SW3.1 U10.1 U14.1 | length 25.4
  Top Layer w0.5: SW3.1 120.195,96.299 120.935,97.039 122.335,97.039 v1@122.425,97.129
  Bottom Layer w0.25: U14.1 112.665,83.269 114.405,85.009 118.205,85.009 122.155,88.959 122.155,93.209 121.245,94.119 121.245,95.116 121.635,95.506 121.635,96.309 122.467,97.141 U10.1
  other v1: 122.435,97.129
VBUS: C2.1 C33.1 U1.10 U12.AD2 USB2.A4 USB2.A9 USB2.B4 USB2.B9 | length 24.6
  Top Layer w0.3: v1(112.185,103.329) 112.185,101.339 114.945,98.579 114.945,95.769 114.954,95.759 114.735,95.759 114.425,95.449 U12.AD2 ; 114.955,98.559 115.615,98.559 117.475,100.419 U1.10
  Bottom Layer w0.25: USB2.B9 107.515,101.569 107.975,101.109 111.665,101.109 112.315,101.759 USB2.A9
  other v1: 114.915,95.789
VDD: C3.1 C12.2 C13.2 C25.2 C26.2 C29.1 C30.1 C31.1 C32.1 C39.1 L4.2 OSC1.4 R1.1 R30.1 R31.1 U5.3 U5.4 U7.A2 U9.8 U12.A22 U12.AD14 U12.AD23 U12.B1 U12.W1 U12.Y2 | length 71.5
  Top Layer w0.1: U12.W1@114.919,91.273 U12.W1@114.925,91.273 ; U12.W1 v1@115.089,91.435
  Top Layer w0.15: v1(107.755,93.629) 108.135,93.629 108.925,92.839 U12.AD23 ; U12.AD14 111.425,93.289 v1(111.435,93.299)
  Top Layer w0.2: U7.A2 106.915,96.019 106.915,94.539 107.755,93.699 v1(107.755,93.629) ; U12.B1 114.905,86.75 114.905,85.649 C29.1
  Top Layer w0.25: C13.2 104.795,87.029 OSC1.4 103.255,84.684 103.255,83.919 103.695,83.479 104.155,83.479 104.765,82.869 109.225,82.869 109.435,83.079 109.967,83.079 ; U12.A22 109.465,86.231 C31.1 109.597,84.846 R1.1 109.967,83.079 ; U12.Y2@114.428,91.529 v1@114.995,91.529 ; v1@115.005,91.699 115.005,91.949 116.225,93.169 C3.1 ; C29.1 116.265,85.249 117.455,86.439 117.455,88.289 118.145,88.979 ; 116.216,85.21 116.216,84.17 114.835,82.789 110.261,82.789 110.125,82.929 110.117,82.929 109.967,83.079 ; 118.155,88.979 118.155,89.349
  Top Layer w0.5: v1@115.164,91.529 116.385,91.529 U5.4 118.155,91.229 ; U5.3 118.155,91.229 ; v2(122.865,91.689) 122.84,91.664 122.84,91.064 122.38,90.604 121.51,90.604 C25.2 C26.2 121.435,89.399 120.815,88.779 119.347,88.779 119.277,88.849 118.655,88.849 118.155,89.349 118.155,91.229
  Bottom Layer w0.2: v1(111.435,93.299) 111.824,93.299 C30.1 ; C39.1 112.285,91.159 112.735,91.609 ; v1(116.235,93.759) 116.235,93.829 117.415,95.009 117.415,96.352 118.512,97.449 R31.1 R30.1
  Bottom Layer w0.5: v1(107.755,93.629) 108.115,93.269 108.115,92.299 108.776,91.638 112.706,91.638 112.735,91.609 112.903,91.609 ; C30.1 112.105,93.099 112.105,92.924 112.135,92.894 112.135,92.665 112.465,92.335 112.465,92.331 112.965,91.831 112.965,91.67 112.903,91.609 ; v1(114.995,91.609) 112.903,91.609
VIN: C24.2 C27.1 R27.1 U1.1 U9.2 | length 11.4
  Top Layer w0.2: v1(118.585,95.449) 118.975,95.059 121.485,95.059 122.265,94.279 U9.2
  Top Layer w0.5: v1(118.585,95.449) 118.585,95.519 118.725,95.659 C27.1 118.725,99.059 C24.2 118.735,99.899 119.575,100.739 119.575,100.989 119.585,100.999
VOUT1: CN1.4 CN1.7 U7.A1 | length 6.3
  Top Layer w0.1: CN1.4@109.295,97.909 CN1.4
  Top Layer w0.2: U7.A1 106.834,96.499 108.975,96.499 109.305,96.829 110.165,95.969 CN1.7 ; 109.295,96.839 CN1.4@109.295,97.909
XC1: OSC1.3 U12.B24 | length 1.7
  Top Layer w0.2: OSC1.3 107.401,86.224 107.948,86.771 U12.B24
XL1: U5.1 U12.D2 | length 5
  Top Layer w0.1: U12.D2 114.706,87.521 114.806,87.621 116.766,87.621 117.145,87.999 117.145,89.469 U5.1
pads on no net: SW3.4 SW3.5 U1.11 U11.2 U12.A8 U12.A10 U12.A12 U12.A14 U12.A16 U12.A20 U12.B9 U12.B11 U12.B13 U12.B15 U12.B17 U12.B19 U12.P23 U12.R24 U12.T23 U12.U24 U12.V23 U12.W24 U12.Y23 USB2.0 USB2.A8 USB2.B8

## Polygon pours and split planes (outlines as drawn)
GND on Bottom Layer (solid, remove dead copper, pour order 6): 130.444,97.189 ccw(c109.455,97.189) 88.465,97.189 ccw(c109.455,97.189)
GND on Top Layer (solid, remove dead copper, pour order 0): 99.305,93.849 105.405,93.849 105.855,93.399 105.855,90.609 107.815,88.649 109.105,88.649 109.105,87.899 109.115,87.889 108.985,87.759 107.015,87.759 106.755,88.019 106.425,88.019 106.255,88.189 97.565,88.189 94.805,90.949 94.805,93.859 99.295,93.859
NONE on Bottom Layer (solid, remove dead copper, pour order 4): 94.745,103.389 104.175,103.389 104.205,103.359 104.205,93.879 104.215,93.869 94.785,93.869 94.745,93.909
GND on Top Layer (solid, remove dead copper, pour order 2): 114.565,95.089 117.555,95.089 117.585,95.059 118.375,95.059 118.905,94.529 118.905,93.909 118.825,93.829 118.345,93.829 118.125,93.609 118.125,92.989 118.065,92.929 116.905,92.929 116.595,93.239 116.595,94.119 116.445,94.269 114.605,94.269 114.565,94.309

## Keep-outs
Board Outline Layer:
  circle w0.025: c118.765,105.379 r1
  region: 119.765,105.379 cw(c118.765,105.379) 117.765,105.379 cw(c118.765,105.379)
  circle w0.025: c118.765,87.379 r1
  region: 119.765,87.379 cw(c118.765,87.379) 117.765,87.379 cw(c118.765,87.379)
  circle w0.025: c100.765,87.379 r1
  region: 101.765,87.379 cw(c100.765,87.379) 99.765,87.379 cw(c100.765,87.379)
  circle w0.025: c100.765,105.379 r1
  region: 101.765,105.379 cw(c100.765,105.379) 99.765,105.379 cw(c100.765,105.379)
  region: 76.2,106.454 85.7,106.454 85.7,96.954 76.2,96.954
  lines w0.254: 105.129,110.645 ccw(c109.765,96.379) 114.4,110.645

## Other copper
Top Layer:
  region: 99.18,103.003 99.18,101.753 97.18,101.753 97.18,103.003
  region net $1N13722: 99.164,96.135 99.164,94.885 97.164,94.885 97.164,96.135
  region net FEED: 98.672,92.843 98.672,91.827 97.656,91.827 97.656,92.843
  region net $1N13722: 98.672,94.113 98.672,93.097 97.656,93.097 97.656,94.113
  region net FEED: 103.065,90.849 103.555,90.849 103.555,89.839 103.065,89.839
Bottom Layer:
  region net NFC2: 105.415,101.019 106.075,101.019 106.075,99.109 105.415,99.109
  region net NFC1: 106.475,101.049 107.155,101.049 107.155,99.109 106.475,99.109

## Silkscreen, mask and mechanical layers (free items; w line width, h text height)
Bottom Silkscreen Layer:
  drawing of 16 lines, arcs and shapes, not listed
Bottom Solder Mask Layer:
  region: 105.575,100.659 106.075,100.659 106.075,99.119 105.575,99.119
  region: 106.465,100.659 106.965,100.659 106.965,99.119 106.465,99.119
Mechanical Layer:
  circle w0.025: c118.765,105.379 r1
  circle w0.025: c118.765,87.379 r1
  circle w0.025: c100.765,87.379 r1
  circle w0.025: c100.765,105.379 r1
